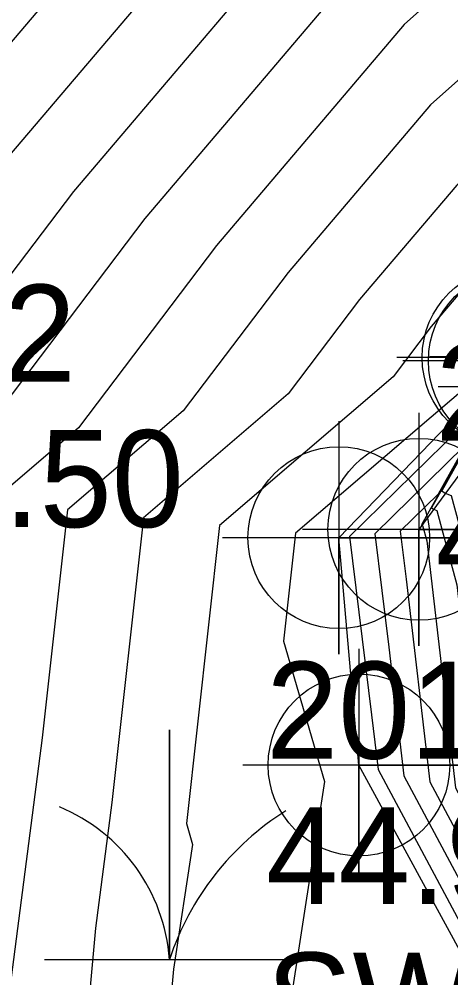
# Model space of a CAD drawing. Extents: x 2090860 to 2091277, y 159470 to 160080.
# Drawn here: x 2091044.64 to 2091055.79, y 159718.96 to 159743.67 of the extents above; entities that cross this region are included whole.
import ezdxf

# ---------------------------------------------------------------- set-up
doc = ezdxf.new("R2010")
doc.units = 0
for name, color, linetype in [('DTM Contours Major', 7, 'Continuous'), ('DTM Contours Minor', 7, 'Continuous'), ('Exist Building', 7, 'Continuous'), ('Exist Building Cogo Point CELL', 7, 'Continuous'), ('Exist DTM Breakline', 7, 'Continuous'), ('Exist DTM Breakline Cogo Elevation', 7, 'Continuous'), ('Exist DTM Breakline Cogo Number', 7, 'Continuous'), ('Exist DTM Breakline Cogo Point CELL', 7, 'Continuous'), ('Exist DTM Regular Point Underwater Cogo Elevation', 7, 'Continuous'), ('Exist DTM Regular Point Underwater Cogo Number', 7, 'Continuous'), ('Exist Hydro Swamp or Marsh', 7, 'Continuous'), ('Exist Hydro Swamp or Marsh Cogo Comment', 7, 'Continuous'), ('Exist Hydro Swamp or Marsh Cogo Elevation', 7, 'Continuous'), ('Exist Hydro Swamp or Marsh Cogo Number', 7, 'Continuous')]:
    doc.layers.add(name, color=color, linetype=linetype)

msp = doc.modelspace()

# ---------------------------------------------------------------- linework, layer by layer
at = {"layer": 'DTM Contours Major'}
for points in [[(2091087.501, 159783.333), (2091087.769, 159779.288), (2091084.366, 159766.629), (2091076.14, 159769.26), (2091074.973, 159768.174), (2091066.061, 159756.411), (2091053.904, 159745.604), (2091047.888, 159738.533), (2091043.463, 159732.701), (2091041.966, 159731.422), (2091041.639, 159728.479), (2091039.685, 159713.437), (2091038.871, 159704.507), (2091038.64, 159701.617), (2091029.076, 159698.576), (2091027.234, 159702.684), (2091029.528, 159709.044), (2091030.086, 159713.086), (2091034.203, 159729.856), (2091026.977, 159732.23), (2091019.254, 159724.332), (2091013.442, 159718.102), (2090999.017, 159707.674), (2090991.506, 159701.21)], [(2091099.154, 159783.181), (2091099.586, 159776.685), (2091095.347, 159760.92), (2091094.892, 159756.071), (2091093.367, 159756.873), (2091092.489, 159757.381), (2091091.65, 159757.144), (2091080.908, 159760.58), (2091079.033, 159758.835), (2091075.343, 159753.965), (2091056.615, 159737.315), (2091055.277, 159735.743), (2091054.293, 159734.446), (2091049.816, 159730.618), (2091048.96, 159722.933), (2091049.119, 159722.392), (2091048.623, 159719.182), (2091046.944, 159700.747), (2091046.379, 159693.703), (2091023.075, 159686.293)], [(2091109.918, 159718.472), (2091105.9, 159728.566), (2091101.492, 159739.908), (2091098.461, 159748.511), (2091097.821, 159750.345), (2091097.24, 159750.65), (2091089.505, 159755.131), (2091088.96, 159754.976), (2091084.801, 159753.611), (2091084.572, 159753.055), (2091082.494, 159751.437), (2091077.793, 159749.325), (2091058.398, 159735.631), (2091057.424, 159734.927), (2091055.456, 159731.425), (2091054.477, 159730.468), (2091054.63, 159729.231), (2091055.24, 159724.01), (2091065.545, 159704.781), (2091068.165, 159699.625), (2091069.803, 159696.726), (2091071.248, 159693.989), (2091077.176, 159683.472), (2091085.357, 159667.475)]]:
    msp.add_lwpolyline(points, dxfattribs=at)
at = {"layer": 'DTM Contours Minor'}
for points in [[(2091090.414, 159783.295), (2091090.724, 159778.637), (2091086.804, 159764.06), (2091077.332, 159767.09), (2091075.988, 159765.839), (2091068.382, 159755.8), (2091054.582, 159743.532), (2091049.736, 159737.835), (2091046.17, 159733.137), (2091043.929, 159731.221), (2091043.438, 159726.812), (2091041.995, 159715.704), (2091040.889, 159703.567), (2091040.574, 159699.638), (2091027.576, 159695.505), (2091025.072, 159701.089), (2091028.191, 159709.733), (2091028.948, 159715.227), (2091032.299, 159728.875), (2091026.418, 159730.808), (2091020.133, 159724.38), (2091013.758, 159717.546), (2090997.937, 159706.109), (2090991.874, 159700.892)], [(2091093.328, 159783.257), (2091093.678, 159777.986), (2091089.243, 159761.491), (2091078.524, 159764.92), (2091077.003, 159763.504), (2091070.702, 159755.188), (2091055.259, 159741.46), (2091051.583, 159737.138), (2091048.878, 159733.573), (2091045.891, 159731.02), (2091045.237, 159725.146), (2091044.305, 159717.971), (2091042.908, 159702.627), (2091042.509, 159697.66), (2091026.075, 159692.434), (2091022.911, 159699.494), (2091026.853, 159710.423), (2091027.811, 159717.368), (2091030.395, 159727.895), (2091025.859, 159729.385), (2091021.012, 159724.428), (2091014.074, 159716.991), (2090996.857, 159704.544), (2090992.242, 159700.573)], [(2091096.241, 159783.219), (2091096.632, 159777.335), (2091091.681, 159758.923), (2091079.716, 159762.75), (2091078.018, 159761.17), (2091073.023, 159754.576), (2091055.937, 159739.388), (2091053.43, 159736.44), (2091051.585, 159734.01), (2091047.854, 159730.819), (2091047.036, 159723.479), (2091046.615, 159720.238), (2091044.926, 159701.687), (2091044.444, 159695.681), (2091024.575, 159689.363), (2091020.749, 159697.899), (2091025.515, 159711.112), (2091026.673, 159719.509), (2091028.491, 159726.914), (2091025.301, 159727.962), (2091021.891, 159724.475), (2091014.39, 159716.435), (2090995.777, 159702.98), (2090992.609, 159700.254)], [(2091102.068, 159783.144), (2091102.54, 159776.034), (2091100.183, 159767.269), (2091098.84, 159752.951), (2091094.335, 159755.317), (2091091.743, 159756.818), (2091089.266, 159756.117), (2091082.1, 159758.41), (2091080.048, 159756.5), (2091077.664, 159753.353), (2091057.292, 159735.243), (2091057.124, 159735.045), (2091057, 159734.882), (2091051.778, 159730.417), (2091051.468, 159727.633), (2091052.528, 159724.019), (2091049.213, 159702.565), (2091048.962, 159699.806), (2091048.314, 159691.724), (2091021.574, 159683.222)], [(2091078.907, 159781.24), (2091077.051, 159774.335), (2091072.564, 159775.771), (2091071.927, 159775.178), (2091059.099, 159758.246), (2091051.871, 159751.82), (2091042.347, 159740.625), (2091037.107, 159733.72), (2091028.653, 159736.498), (2091016.618, 159724.19), (2091012.493, 159719.768), (2091002.257, 159712.368), (2090990.403, 159702.167)], [(2091081.861, 159780.589), (2091079.489, 159771.767), (2091073.756, 159773.601), (2091072.942, 159772.843), (2091061.42, 159757.634), (2091052.549, 159749.748), (2091044.194, 159739.928), (2091038.048, 159731.828), (2091038.042, 159731.823), (2091038.04, 159731.812), (2091035.064, 159708.902), (2091034.835, 159706.388), (2091034.77, 159705.574), (2091032.077, 159704.717), (2091031.558, 159705.874), (2091032.204, 159707.665), (2091032.361, 159708.804), (2091038.011, 159731.817), (2091028.095, 159735.075), (2091017.497, 159724.237), (2091012.809, 159719.213), (2091001.177, 159710.803), (2090990.771, 159701.848)], [(2091084.815, 159779.939), (2091081.928, 159769.198), (2091074.948, 159771.43), (2091073.958, 159770.509), (2091063.74, 159757.023), (2091053.226, 159747.676), (2091046.041, 159739.23), (2091040.755, 159732.265), (2091040.004, 159731.622), (2091039.84, 159730.145), (2091037.374, 159711.17), (2091036.853, 159705.448), (2091036.705, 159703.595), (2091030.576, 159701.647), (2091029.396, 159704.279), (2091030.866, 159708.355), (2091031.224, 159710.945), (2091036.107, 159730.837), (2091027.536, 159733.653), (2091018.376, 159724.285), (2091013.126, 159718.657), (2091000.097, 159709.239), (2090991.138, 159701.529)], [(2091110.18, 159720.929), (2091102.507, 159740.673), (2091102.076, 159741.898), (2091098.523, 159752.07), (2091095.303, 159753.762), (2091090.997, 159756.256), (2091086.882, 159755.091), (2091083.292, 159756.24), (2091081.063, 159754.166), (2091079.984, 159752.742), (2091069.862, 159743.743), (2091057.692, 159735.151), (2091057.4, 159734.94), (2091056.81, 159733.89), (2091053.174, 159730.332), (2091053.742, 159725.736), (2091053.907, 159724.325), (2091066.94, 159700.006), (2091067.301, 159699.295), (2091070.185, 159694.19), (2091070.474, 159693.642), (2091081.681, 159673.757)], [(2091108.04, 159724.748), (2091102, 159740.29), (2091100.269, 159745.204), (2091098.172, 159751.208), (2091096.272, 159752.206), (2091090.251, 159755.693), (2091084.499, 159754.065), (2091084.484, 159754.07), (2091084.431, 159754.02), (2091081.99, 159752.118), (2091081.294, 159751.805), (2091058.045, 159735.391), (2091057.412, 159734.933), (2091056.133, 159732.658), (2091053.826, 159730.4), (2091054.186, 159727.483), (2091054.574, 159724.168), (2091066.243, 159702.393), (2091067.733, 159699.46), (2091069.994, 159695.458), (2091070.861, 159693.815), (2091079.429, 159678.614), (2091085.16, 159667.407)], [(2091109.431, 159718.14), (2091103.76, 159732.384), (2091100.985, 159739.525), (2091098.275, 159747.218), (2091097.012, 159749.764), (2091089.63, 159754.028), (2091089.296, 159754.532), (2091085.115, 159753.16), (2091084.654, 159752.045), (2091082.998, 159750.755), (2091074.292, 159746.844), (2091058.751, 159735.872), (2091057.436, 159734.921), (2091055.026, 159730.634), (2091055.037, 159730.627), (2091055.054, 159730.62), (2091055.163, 159730.22), (2091055.907, 159723.852), (2091064.848, 159707.168), (2091068.598, 159699.79), (2091069.612, 159697.994), (2091071.635, 159694.163), (2091074.923, 159688.329), (2091081.29, 159675.881)], [(2091108.943, 159717.808), (2091101.62, 159736.202), (2091100.477, 159739.143), (2091099.361, 159742.31), (2091095.844, 159749.404), (2091089.856, 159752.863), (2091089.15, 159753.93), (2091085.428, 159752.708), (2091084.737, 159751.036), (2091083.503, 159750.074), (2091070.791, 159744.363), (2091059.104, 159736.112), (2091057.447, 159734.915), (2091055.289, 159731.075), (2091055.34, 159731.038), (2091055.423, 159731.007), (2091055.943, 159729.091), (2091056.573, 159723.695), (2091064.15, 159709.555)], [(2091107.547, 159719.758), (2091100.062, 159737.927), (2091099.686, 159738.852), (2091099.347, 159739.624), (2091094.676, 159749.044), (2091090.082, 159751.698), (2091089.004, 159753.327), (2091085.742, 159752.256), (2091084.82, 159750.026), (2091084.007, 159749.393), (2091067.289, 159741.882), (2091059.458, 159736.353), (2091057.459, 159734.908), (2091055.552, 159731.515), (2091055.643, 159731.449), (2091055.791, 159731.394), (2091056.723, 159727.962), (2091057.24, 159723.537), (2091063.453, 159711.942), (2091068.62, 159701.777), (2091069.717, 159700.26), (2091072.599, 159695.395), (2091072.913, 159694.755), (2091083.535, 159676.648)]]:
    msp.add_lwpolyline(points, dxfattribs=at)
at = {"layer": 'Exist Building'}
msp.add_line((2091058.231, 159734.962), (2091054.957, 159730.518), dxfattribs=at)
at = {"layer": 'Exist Building Cogo Point CELL'}
for points in [[(2091057.549, 159737.861), (2091057.549, 159731.861), (2091057.549, 159734.861), (2091060.549, 159734.861), (2091054.549, 159734.861)], [(2091058.231, 159737.962), (2091058.231, 159731.962), (2091058.231, 159734.962), (2091061.231, 159734.962), (2091055.231, 159734.962)], [(2091054.957, 159733.518), (2091054.957, 159727.518), (2091054.957, 159730.518), (2091057.957, 159730.518), (2091051.957, 159730.518)]]:
    msp.add_lwpolyline(points, dxfattribs=at)
for centre in [(2091057.549, 159734.861), (2091054.957, 159730.518)]:
    msp.add_circle(centre, 2.344, dxfattribs=at)
at = {"layer": 'Exist DTM Breakline'}
msp.add_lwpolyline([(2091168.326, 159489.347), (2091148.612, 159530.829), (2091132.315, 159565.389), (2091116.339, 159597.574), (2091098.698, 159637.587), (2091084.7, 159667.248), (2091067.163, 159699.242), (2091053.414, 159724.442), (2091052.893, 159730.303), (2091057.39, 159734.945)], dxfattribs=at)
at = {"layer": 'Exist DTM Breakline Cogo Point CELL'}
for points in [[(2091057.39, 159737.945), (2091057.39, 159731.945), (2091057.39, 159734.945), (2091060.39, 159734.945), (2091054.39, 159734.945)], [(2091058.458, 159737.195), (2091058.458, 159731.195), (2091058.458, 159734.195), (2091061.458, 159734.195), (2091055.458, 159734.195)], [(2091052.893, 159733.303), (2091052.893, 159727.303), (2091052.893, 159730.303), (2091055.893, 159730.303), (2091049.893, 159730.303)], [(2091053.414, 159727.442), (2091053.414, 159721.442), (2091053.414, 159724.442), (2091056.414, 159724.442), (2091050.414, 159724.442)]]:
    msp.add_lwpolyline(points, dxfattribs=at)
for centre in [(2091057.39, 159734.945), (2091052.893, 159730.303), (2091053.414, 159724.442)]:
    msp.add_circle(centre, 2.344, dxfattribs=at)
at = {"layer": 'Exist Hydro Swamp or Marsh'}
msp.add_line((2091048.519, 159722.106), (2091048.519, 159722.106), dxfattribs=at)
msp.add_lwpolyline([(2091045.294, 159719.432), (2091048.52, 159719.432), (2091048.52, 159725.349), (2091048.52, 159719.432), (2091051.745, 159719.432)], dxfattribs=at)
for centre, radius, start, end in [((2091043.92, 159719.099), 4.612, 4.1403, 67.535), ((2091055.361, 159717.159), 7.208, 122.1274, 161.6222)]:
    msp.add_arc(centre, radius, start, end, dxfattribs=at)

# ---------------------------------------------------------------- texts
at = {"layer": 'Exist DTM Breakline Cogo Elevation'}
msp.add_text('45.39', height=2.5, dxfattribs=at).set_placement((2091055.393, 159729.053))
at = {"layer": 'Exist DTM Breakline Cogo Number'}
msp.add_text('203', height=2.5, dxfattribs=at).set_placement((2091055.393, 159732.803))
at = {"layer": 'Exist DTM Regular Point Underwater Cogo Elevation'}
msp.add_text('43.50', height=2.5, dxfattribs=at).set_placement((2091040.526, 159730.575))
at = {"layer": 'Exist DTM Regular Point Underwater Cogo Number'}
msp.add_text('442', height=2.5, dxfattribs=at).set_placement((2091040.526, 159734.325))
at = {"layer": 'Exist Hydro Swamp or Marsh Cogo Comment'}
msp.add_text('SWAMP AREA', height=2.5, dxfattribs=at).set_placement((2091051.019, 159717.106))
at = {"layer": 'Exist Hydro Swamp or Marsh Cogo Elevation'}
msp.add_text('44.96', height=2.5, dxfattribs=at).set_placement((2091051.019, 159720.856))
at = {"layer": 'Exist Hydro Swamp or Marsh Cogo Number'}
msp.add_text('201', height=2.5, dxfattribs=at).set_placement((2091051.019, 159724.606))

doc.saveas('drawing.dxf')
